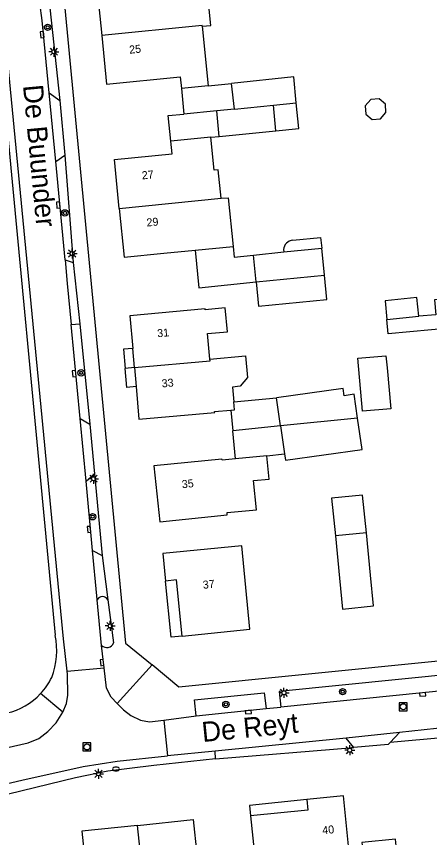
# Model space of a CAD drawing. Extents: x 140000 to 143000, y 403500 to 406000.
# Drawn here: x 140499.3 to 140550.9, y 403674.1 to 403776.7 of the extents above; entities that cross this region are included whole.
import ezdxf

# ---------------------------------------------------------------- set-up
doc = ezdxf.new("R2010")
doc.units = 0
for name, color, linetype in [('gg-afsc-erfafscheiding', 7, 'Continuous'), ('gg-anno-huisnummerreeks BGT', 7, 'Continuous'), ('gg-anno-openbare ruimte label', 7, 'Continuous'), ('gg-bbg-bijgebouw', 7, 'Continuous'), ('gg-bbg-gedigitaliseerde bebouwing', 7, 'Continuous'), ('gg-bbg-gedigitaliseerde bijgebouw', 7, 'Continuous'), ('gg-bbg-hoofdgebouw', 7, 'Continuous'), ('gg-bbg-luifel en loopbrug', 7, 'Continuous'), ('gg-bbg-tussenscheiding', 7, 'Continuous'), ('gg-knt-verharding', 7, 'Continuous'), ('gg-knt-verharding nz', 7, 'Continuous'), ('gt-symb-boom', 7, 'Continuous'), ('gt-symb-brandkraan', 7, 'Continuous'), ('gt-symb-kolk', 7, 'Continuous'), ('gt-symb-lichtmast', 7, 'Continuous'), ('gt-symb-rioolschacht', 7, 'Continuous')]:
    doc.layers.add(name, color=color, linetype=linetype)

# ---------------------------------------------------------------- blocks, each defined once
blk = doc.blocks.new('gt0-KOLK')
at = {"layer": 'gt-symb-kolk'}
blk.add_lwpolyline([(0, 0), (0.38, 0), (0.38, 0.4), (-0.37, 0.4), (-0.37, 0), (0, 0)], dxfattribs=at)
blk = doc.blocks.new('gt0-BOOM')
at = {"layer": 'gt-symb-boom'}
for radius in [0.4, 0.2]:
    blk.add_circle((0, 0), radius, dxfattribs=at)
blk = doc.blocks.new('gt0-LMAST')
at = {"layer": 'gt-symb-lichtmast'}
for p, q in [((-0.18, 0.17), (-0.45, 0.44)), ((-0.01, 0.25), (-0.01, 0.62)), ((0.17, 0.17), (0.44, 0.44)), ((-0.26, 0), (-0.63, 0)), ((-0.18, -0.18), (-0.45, -0.45)), ((-0.01, -0.25), (-0.01, -0.63)), ((0.44, -0.45), (0.17, -0.18)), ((0.24, 0), (0.62, 0))]:
    blk.add_line(p, q, dxfattribs=at)
blk.add_circle((-0.01, 0), 0.25, dxfattribs=at)
blk = doc.blocks.new('gt0-RS')
at = {"layer": 'gt-symb-rioolschacht'}
blk.add_lwpolyline([(-0.5, -0.5), (0.5, -0.5), (0.5, 0.5), (-0.5, 0.5)], close=True, dxfattribs=at)
blk.add_circle((0, 0), 0.375, dxfattribs=at)
blk = doc.blocks.new('gt0-BR')
at = {"layer": 'gt-symb-brandkraan'}
for centre, radius, start, end in [((-0.24, 0), 0.206, 107.5669, 252.4331), ((0.6, -2.66), 3, 106.892, 107.5669), ((0, -0.69), 0.938, 73.108, 106.892), ((-0.6, -2.66), 3, 72.4331, 73.108), ((0.24, 0), 0.206, 287.567, 72.4331), ((0.6, 2.66), 3, 252.4331, 253.108), ((0, 0.69), 0.938, 253.108, 286.8921), ((-0.6, 2.66), 3, 286.8921, 287.567)]:
    blk.add_arc(centre, radius, start, end, dxfattribs=at)

msp = doc.modelspace()

# ---------------------------------------------------------------- linework, layer by layer
at = {"layer": 'gg-afsc-erfafscheiding'}
msp.add_line((140524.21, 403683.93), (140541.48, 403685.34), dxfattribs=at)
at = {"layer": 'gg-bbg-bijgebouw'}
for p, q in [((140526.57, 403765.08), (140526.21, 403768.27)), ((140532.73, 403747.24), (140537.46, 403747.72)), ((140537.8, 403744.33), (140537.46, 403747.72)), ((140528.93, 403746.85), (140532.73, 403747.24)), ((140529.27, 403743.48), (140528.93, 403746.85)), ((140532.32, 403725.5), (140531.82, 403729.02)), ((140532.32, 403725.5), (140532.8, 403722.03)), ((140543.05, 403712.16), (140539.17, 403711.78))]:
    msp.add_line(p, q, dxfattribs=at)
for points in [[(140534.29, 403765.86), (140533.98, 403769.1), (140526.21, 403768.27)], [(140529.27, 403743.48), (140529.57, 403740.44), (140538.1, 403741.3), (140537.8, 403744.33)], [(140546.09, 403727.64), (140542.55, 403727.33), (140541.96, 403733.95), (140545.48, 403734.26), (140545.64, 403732.76), (140546.09, 403727.64)], [(140541.95, 403726.49), (140541.54, 403729.45), (140540.27, 403729.27), (140540.14, 403730.19), (140531.82, 403729.02)], [(140532.8, 403722.03), (140532.92, 403721.21), (140542.5, 403722.56), (140541.95, 403726.49)], [(140539.17, 403711.78), (140539.69, 403706.49), (140540.08, 403702.62), (140543.95, 403703.05), (140543.57, 403706.87), (140543.05, 403712.16)]]:
    msp.add_lwpolyline(points, dxfattribs=at)
at = {"layer": 'gg-bbg-gedigitaliseerde bebouwing'}
msp.add_line((140523.62, 403761.56), (140518.61, 403761.06), dxfattribs=at)
at = {"layer": 'gg-bbg-gedigitaliseerde bijgebouw'}
for p, q in [((140526.57, 403765.08), (140524.36, 403764.86)), ((140531.43, 403765.57), (140534.29, 403765.86)), ((140531.74, 403762.36), (140531.43, 403765.57)), ((140524.67, 403761.66), (140524.36, 403764.86)), ((140524.67, 403761.66), (140531.74, 403762.36))]:
    msp.add_line(p, q, dxfattribs=at)
at = {"layer": 'gg-bbg-hoofdgebouw'}
for p, q in [((140522.53, 403775.42), (140523.27, 403767.96)), ((140523.27, 403767.96), (140519.93, 403767.63)), ((140521.64, 403747.46), (140526.4, 403747.93)), ((140514.05, 403732.8), (140513.84, 403735.19)), ((140514.05, 403732.8), (140514.26, 403730.41)), ((140530.6, 403721.77), (140526.7, 403721.39))]:
    msp.add_line(p, q, dxfattribs=at)
for points in [[(140512.86, 403780.69), (140509.37, 403780.35), (140509.98, 403774.28)], [(140522.53, 403775.42), (140523.62, 403775.53), (140523.04, 403781.33), (140518.92, 403780.92), (140518.89, 403781.27), (140518.33, 403781.21)], [(140509.98, 403774.28), (140510.59, 403768.17), (140519.78, 403769.1), (140519.93, 403767.63)], [(140512.16, 403752.67), (140511.55, 403758.76), (140518.77, 403759.48), (140518.61, 403761.06)], [(140524.9, 403753.93), (140524.54, 403757.48), (140524.03, 403757.43), (140523.62, 403761.56)], [(140524.9, 403753.93), (140525.79, 403754.01), (140526.4, 403747.93)], [(140512.16, 403752.67), (140512.76, 403746.59), (140517.74, 403747.08), (140521.64, 403747.46)], [(140523.49, 403733.83), (140523.2, 403737.04), (140525.68, 403737.27), (140525.41, 403740.25), (140522.92, 403740.02), (140522.91, 403740.12), (140513.47, 403739.26), (140513.84, 403735.19)], [(140523.49, 403733.83), (140527.93, 403734.27), (140528.2, 403731.56), (140527.27, 403730.45), (140526.32, 403730.34), (140526.49, 403728.53)], [(140514.26, 403730.41), (140514.63, 403726.33), (140524.09, 403727.19), (140524.08, 403727.3), (140526.11, 403727.49)], [(140526.11, 403727.49), (140526.58, 403727.53), (140526.49, 403728.53)], [(140526.7, 403721.39), (140525.01, 403721.22), (140524.99, 403721.37), (140516.5, 403720.51), (140517.23, 403713.54), (140525.67, 403714.4), (140525.65, 403714.67), (140529.3, 403715.03), (140528.94, 403718.67), (140530.89, 403718.86), (140530.6, 403721.77)], [(140520.01, 403699.26), (140528.49, 403700.11), (140527.47, 403710.54), (140517.62, 403709.58), (140517.96, 403706.13)], [(140520.01, 403699.26), (140519.3, 403706.27), (140517.96, 403706.13)], [(140528.58, 403676.8), (140529.43, 403668.44), (140542.8, 403669.81), (140543.07, 403667.19), (140543.73, 403660.82), (140547.9, 403661.25), (140547.29, 403667.62), (140546.67, 403673.87), (140542.49, 403673.46), (140542.55, 403672.81), (140540.85, 403672.64), (140540.19, 403679.28), (140535.62, 403678.82)], [(140535.62, 403678.82), (140535.74, 403677.5), (140528.58, 403676.8)], [(140514.45, 403675.61), (140521.41, 403676.34), (140522.32, 403667.67)], [(140514.45, 403675.61), (140507.49, 403674.89), (140508.41, 403666.11)]]:
    msp.add_lwpolyline(points, dxfattribs=at)
at = {"layer": 'gg-bbg-luifel en loopbrug'}
for p, q in [((140523.27, 403767.96), (140526.21, 403768.27)), ((140519.93, 403767.63), (140520.25, 403764.45)), ((140524.36, 403764.86), (140520.25, 403764.45)), ((140523.62, 403761.56), (140524.67, 403761.66)), ((140532.7, 403747.52), (140532.73, 403747.24)), ((140545.61, 403738.8), (140549.59, 403739.19)), ((140514.05, 403732.8), (140512.9, 403732.69)), ((140526.49, 403728.53), (140531.82, 403729.02)), ((140526.11, 403727.49), (140526.35, 403724.89)), ((140532.32, 403725.5), (140526.35, 403724.89)), ((140526.7, 403721.39), (140526.35, 403724.89)), ((140530.6, 403721.77), (140532.8, 403722.03))]:
    msp.add_line(p, q, dxfattribs=at)
for points in [[(140542.99, 403764.45), (140543.77, 403763.77), (140544.81, 403763.85), (140545.49, 403764.63), (140545.42, 403765.67), (140544.63, 403766.35), (140543.59, 403766.28), (140542.91, 403765.49), (140542.99, 403764.45)], [(140531.74, 403762.36), (140534.6, 403762.64), (140534.29, 403765.86)], [(140518.61, 403761.06), (140518.29, 403764.26), (140520.25, 403764.45)], [(140533.85, 403748.7), (140537.32, 403749.05), (140537.46, 403747.72)], [(140526.4, 403747.93), (140526.53, 403746.6), (140528.93, 403746.85)], [(140521.64, 403747.46), (140522.1, 403742.76), (140529.27, 403743.48)], [(140549.59, 403739.19), (140549.37, 403741.53), (140545.39, 403741.14), (140545.61, 403738.8)], [(140553.51, 403741.43), (140551.54, 403741.25), (140551.74, 403739.39), (140549.59, 403739.19)], [(140553.87, 403738.03), (140553.9, 403737.76), (140545.77, 403737.02), (140545.61, 403738.8)], [(140513.84, 403735.19), (140512.69, 403735.08), (140512.9, 403732.69)], [(140514.26, 403730.41), (140513.12, 403730.3), (140512.9, 403732.69)], [(140543.05, 403712.16), (140542.58, 403716.85), (140538.7, 403716.47), (140539.17, 403711.78)], [(140520.01, 403699.26), (140518.65, 403699.12), (140517.96, 403706.13)], [(140535.62, 403678.82), (140528.45, 403678.11), (140528.58, 403676.8)]]:
    msp.add_lwpolyline(points, dxfattribs=at)
msp.add_arc((140533.95, 403747.45), 1.25, 94.2807, 176.8004, dxfattribs=at)
at = {"layer": 'gg-bbg-tussenscheiding'}
for p, q in [((140526.57, 403765.08), (140531.43, 403765.57)), ((140512.16, 403752.67), (140524.9, 403753.93)), ((140529.27, 403743.48), (140537.8, 403744.33)), ((140541.95, 403726.49), (140532.32, 403725.5)), ((140515.89, 403661.72), (140514.45, 403675.61))]:
    msp.add_line(p, q, dxfattribs=at)
for points in [[(140522.53, 403775.42), (140522.52, 403775.51), (140509.98, 403774.28)], [(140514.05, 403732.8), (140523.51, 403733.65), (140523.49, 403733.83)]]:
    msp.add_lwpolyline(points, dxfattribs=at)
at = {"layer": 'gg-knt-verharding'}
for p, q in [((140496.9, 403775.61), (140504.17, 403699.35)), ((140503.41, 403767.12), (140504.74, 403766.15)), ((140504.74, 403766.15), (140505.36, 403759.32)), ((140504.22, 403758.51), (140505.36, 403759.32)), ((140505.36, 403759.32), (140506.41, 403745.91)), ((140505.39, 403746.25), (140504.22, 403758.51)), ((140505.39, 403746.25), (140506.41, 403745.91)), ((140506.41, 403745.91), (140507.23, 403738.25)), ((140506.15, 403738.16), (140507.23, 403738.25)), ((140507.27, 403726.41), (140506.15, 403738.16)), ((140507.23, 403738.25), (140508.48, 403725.74)), ((140507.27, 403726.41), (140508.48, 403725.74)), ((140508.48, 403725.74), (140509.05, 403719.53)), ((140508.01, 403718.59), (140509.05, 403719.53)), ((140509.05, 403719.53), (140510.01, 403709.32)), ((140508.83, 403709.95), (140508.01, 403718.59)), ((140508.83, 403709.95), (140510.01, 403709.32)), ((140510.01, 403709.32), (140510.74, 403703.8)), ((140509.96, 403698.07), (140509.42, 403703.77)), ((140510.74, 403703.8), (140511.45, 403698.39)), ((140510.29, 403695.29), (140509.96, 403698.07)), ((140505.66, 403694.87), (140510.29, 403695.29)), ((140516.27, 403695.64), (140511.92, 403690.85)), ((140570, 403694.18), (140532.36, 403690.38)), ((140505.12, 403689.75), (140502.34, 403692.06)), ((140521.79, 403689.31), (140530.51, 403690.19)), ((140530.51, 403690.19), (140532.36, 403690.38)), ((140579.64, 403690.73), (140547.2, 403687.19)), ((140517.75, 403688.73), (140521.79, 403689.31)), ((140517.75, 403688.73), (140518.2, 403684.28)), ((140547.2, 403687.19), (140546.02, 403685.98)), ((140540.5, 403686.52), (140524.15, 403684.87)), ((140541.48, 403685.34), (140540.5, 403686.52)), ((140524.15, 403684.87), (140518.2, 403684.28)), ((140524.21, 403683.93), (140524.15, 403684.87))]:
    msp.add_line(p, q, dxfattribs=at)
for points in [[(140504.65, 403785.13), (140512.95, 403698.38), (140516.27, 403695.64)], [(140501.82, 403780.26), (140503.21, 403780.48), (140504.74, 403766.15)], [(140503.41, 403767.12), (140502.55, 403776.16), (140502.23, 403778.32), (140501.88, 403779.85), (140501.82, 403780.26)], [(140505.66, 403694.87), (140505.21, 403698.89), (140497.71, 403776.65)], [(140584.86, 403699.42), (140519.6, 403692.89), (140516.27, 403695.64)], [(140511.92, 403690.85), (140511.15, 403691.64), (140510.59, 403692.76), (140510.29, 403695.29)], [(140570, 403694.18), (140569.85, 403696.11), (140532.13, 403692.35), (140532.36, 403690.38)], [(140505.12, 403689.75), (140505.56, 403690.83), (140505.75, 403691.87), (140505.7, 403694.51), (140505.66, 403694.87)], [(140521.79, 403689.31), (140521.57, 403691.3), (140530.29, 403692.17), (140530.51, 403690.19)], [(140511.92, 403690.85), (140512.68, 403690.06), (140513.63, 403689.35), (140514.8, 403688.77), (140515.96, 403688.53), (140517.75, 403688.73)], [(140496.54, 403684.94), (140500.76, 403685.93), (140502.12, 403686.44), (140503.23, 403687.35), (140504.28, 403688.43), (140505.12, 403689.75)], [(140579.8, 403689), (140547.41, 403686.08), (140546.02, 403685.98)], [(140546.02, 403685.98), (140545.77, 403685.73), (140541.48, 403685.34)], [(140497.48, 403680.69), (140500, 403681.27), (140507.65, 403682.96), (140511.89, 403683.64), (140518.2, 403684.28)], [(140524.21, 403683.93), (140516.47, 403683.08), (140510.75, 403682.4), (140506.71, 403681.55), (140493.14, 403678.26), (140477.3, 403674.53), (140473.16, 403673.49), (140470.33, 403672.95), (140468.88, 403672.77), (140465.91, 403672.71), (140464.27, 403672.75), (140461.87, 403673.14), (140460.02, 403673.53), (140458.13, 403674.14), (140456.09, 403675.09), (140454.28, 403676.02), (140452.91, 403676.9), (140452.21, 403677.54)]]:
    msp.add_lwpolyline(points, dxfattribs=at)
for centre, radius, start, end in [((140510.09, 403703.44), 0.744, 28.8452, 154.1879), ((140494.83, 403697.48), 9.52, 339.12, 11.2914), ((140510.6, 403698.74), 0.922, 226.4638, 337.9987), ((140496.31, 403697.68), 8.24, 317.0257, 334.1711), ((140496.3, 403697.69), 8.25, 282.7927, 317.0394)]:
    msp.add_arc(centre, radius, start, end, dxfattribs=at)
at = {"layer": 'gg-knt-verharding nz'}
for p, q in [((140504.22, 403758.51), (140503.41, 403767.12)), ((140508.01, 403718.59), (140507.27, 403726.41)), ((140547.2, 403687.19), (140540.5, 403686.52))]:
    msp.add_line(p, q, dxfattribs=at)
for points in [[(140505.39, 403746.25), (140505.67, 403743.31), (140506.15, 403738.16)], [(140509.42, 403703.77), (140509.37, 403704.29), (140508.83, 403709.95)]]:
    msp.add_lwpolyline(points, dxfattribs=at)

# ---------------------------------------------------------------- block references
at = {"layer": 'gt-symb-boom'}
for p in [(140503.21, 403775.29), (140505.37, 403752.11), (140507.4, 403732.13), (140508.84, 403714.16), (140540.08, 403692.31), (140525.49, 403690.72)]:
    msp.add_blockref('gt0-BOOM', p, dxfattribs=at)
at = {"layer": 'gt-symb-brandkraan'}
msp.add_blockref('gt0-BR', (140511.75, 403682.65), dxfattribs=at)
at = {"layer": 'gt-symb-kolk'}
for p, rotation in [((140502.73, 403774.39), 95.67445806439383), ((140504.74, 403753.11), 95.41508283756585), ((140506.73, 403732.04), 95.41508283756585), ((140508.58, 403712.58), 95.41508283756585), ((140510.21, 403695.97), 96.72963770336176), ((140550.07, 403692.17), -174.23640950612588), ((140528.29, 403689.96), -174.3416034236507)]:
    msp.add_blockref('gt0-KOLK', p, dxfattribs=dict(at, rotation=rotation))
at = {"layer": 'gt-symb-lichtmast'}
for p in [(140504.01, 403772.24), (140506.29, 403747.03), (140508.96, 403718.91), (140511.05, 403700.52), (140532.76, 403692.17), (140540.97, 403685), (140509.57, 403682.05)]:
    msp.add_blockref('gt0-LMAST', p, dxfattribs=at)
at = {"layer": 'gt-symb-rioolschacht'}
for p in [(140547.65, 403690.43), (140508.13, 403685.41)]:
    msp.add_blockref('gt0-RS', p, dxfattribs=at)

# ---------------------------------------------------------------- texts
at = {"layer": 'gg-anno-huisnummerreeks BGT'}
for s, rotation, p in [('25', 5.7, (140513.45, 403771.99)), ('27', 5.6, (140515.03, 403756.29)), ('29', 5.6, (140515.62, 403750.4)), ('31', 5.1, (140516.95, 403736.57)), ('33', 5.1, (140517.51, 403730.3)), ('35', 5.9, (140520.03, 403717.71)), ('37', 5.7, (140522.65, 403705.15)), ('40', 5.7, (140537.58, 403674.49))]:
    msp.add_text(s, height=1, rotation=rotation, dxfattribs=at).set_placement(p)
at = {"layer": 'gg-anno-openbare ruimte label'}
for s, rotation, p in [('De Buunder', 275.4, (140500.13, 403768.02)), ('De Reyt', 5.7, (140522.6, 403686.01))]:
    msp.add_text(s, height=2.5, rotation=rotation, dxfattribs=at).set_placement(p)

doc.saveas('drawing.dxf')
